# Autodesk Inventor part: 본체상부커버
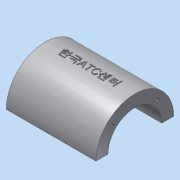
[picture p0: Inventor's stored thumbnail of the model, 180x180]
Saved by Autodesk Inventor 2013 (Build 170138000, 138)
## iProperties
Created: 2015-12
Part Number: 본체상부커버
Material: 알루미늄 6061
Document SubType Name: Modeling
Designer: mduedu
Density: 2.71 g/cm^3
Mass: 175.162 g
Surface Area: 166.445 cm^2
Volume: 64.6353 cm^3
Author: mduedu
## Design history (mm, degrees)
sketch "스케치1"
  geometry: L1 (45, 40)-(-45, 40); L2 (-45, 40)-(-45, -40); L3 (-45, -40)-(45, -40); L4 (45, -40)-(45, 40); L5 (45, 40)-(-45, -40); L6 (-45, 40)-(45, -40); 2 further points
  constraints: 12 end point, 2 midpoint, 2 parallel, 1 coincident, 1 horizontal, 1 perpendicular, 3 other
  dimensions: "d0" = 90 distance of L2.end L3.end; "d2" = 80 distance of L1.end L2.end
extrude "돌출1" new body sketch "스케치1" distance "d3" = 10; taper "d4" = 0 deg
sketch "스케치2"
  geometry: C1 r 32.5 at (80, 0); 1 further point
  constraints: 1 centre point
  dimensions: "d5" = 65 diameter of C1; "d116" = 80 distance of point (0, 0) C1.centre
extrude "돌출2" join sketch "스케치2" stored distance "d7" = 75; taper "d8" = 0 deg
sketch "스케치3"
  geometry: L1 (-27.5, -20)-(27.5, -20); L2 (27.5, -20)-(27.5, 20); L3 (27.5, 20)-(-27.5, 20); L4 (-27.5, 20)-(-27.5, -20); L5 (-27.5, -20)-(27.5, 20); L6 (27.5, -20)-(-27.5, 20); 1 further point
  constraints: 12 end point, 2 midpoint, 2 parallel, 1 horizontal, 1 perpendicular
  dimensions: "d9" = 55 distance of L2.end L3.end; "d11" = 40 distance of L1.end L2.end
extrude "돌출3" new body sketch "스케치3" stored distance "d12" = 75; taper "d13" = 0 deg
fillet "모깎기1"
fillet "모깎기2"
feature "결합1"
  node "솔리드2"
sketch "스케치4"
  geometry: L1 (-37.5, 47.5)-(37.5, 47.5) reference; L2 (32.5, 47.5)-(40.208, 10); L3 (37.5, 47.5)-(37.5, 112.5) reference; L4 (60.208, 0)-(60.208, 10) reference; L5 (60.208, 10)-(-60.208, 10) reference; 1 further point
  constraints: 2 end point, 2 point on line
  dimensions: "d15" = 5 distance from line of L2.start L3; "d117" = 20 distance from line of L2.end L4
sketch "스케치5"
  geometry: L1 (10, 35.208)-(56.729, 22.687); L2 (0, 60.208)-(10, 60.208) reference; L3 (10, -60.208)-(10, 60.208) reference; 2 further points
  constraints: 2 end point, 1 point on line, 2 other
  dimensions: "d118" = 25 distance from line of L1.start L2; "d119" = 75 deg angle of L1 L3
feature "리브1" dims "d19" = 1, "d20" = 6, "d21" = 0, "d22" = 0, "d23" = 1, "d24" = 1
feature "리브2" dims "d25" = 1, "d26" = 6, "d27" = 0, "d28" = 0, "d29" = 1, "d30" = 1
fillet "모깎기4" dims "d31" = 2
fillet "모깎기5" dims "d32" = 2
fillet "모깎기6" dims "d33" = 2
sketch "스케치6"
  geometry: L1 (0, 0)-(-32.88, 32.88); L2 (0, 0)-(-46.5, 0); A1 r 46.5 centre (0, 0) between (-32.88, 32.88) and (-46.5, 0); 5 further points
  constraints: 4 end point, 2 coincident, 2 point on circle, 1 centre point, 1 horizontal, 5 other
  dimensions: "d120" = 93 diameter of A1; "d122" = 45 deg angle of L1 L2; "d126" = 360 deg dimension on point (0, 0) point (-32.88, 32.88) (derived)
hole "구멍1" sketch "스케치6" at (-32.88, 32.88), (-32.88, -32.88), (32.88, -32.88), (32.88, 32.88) diameter "d34" = 7; stored, may be unused: countersink angle "d38" = 90 deg, drill point angle "d40" = 118 deg; dims "d35" = 6, "d36" = 12, "d37" = 3, "d39" = 8
fillet "모깎기13" dims "d131" = 3
hole "구멍2" diameter "d44" = 45; stored, may be unused: countersink angle "d48" = 90 deg, drill point angle "d50" = 118 deg; dims "d42" = 10, "d43" = 10, "d45" = 6, "d46" = 4, "d47" = 2, "d49" = 8
sketch "스케치7" dims "d52" = 26.5
  geometry: L1 (0, 0)-(32.5, 0); L2 (0, 0)-(22.981, 22.981); A1 r 32.5 centre (0, 0) between (32.5, 0) and (22.981, 22.981) reference; 3 further points
  constraints: 4 end point, 2 point on circle, 1 coincident, 1 horizontal, 1 point on line, 3 other
  dimensions: "d51" = 45 deg angle of L2 L1
hole "구멍3" sketch "스케치7" at (18.738, 18.738) diameter "d54" = 2.459; stored, may be unused: countersink angle "d58" = 90 deg, drill point angle "d60" = 118 deg; dims "d55" = 8, "d56" = 4, "d57" = 2, "d59" = 10
sketch "스케치9"
  geometry: L1 (-75, -110)-(75, -110); L2 (75, -110)-(75, 0); L3 (75, 0)-(-75, 0); L4 (-75, 0)-(-75, -110); L5 (-60.208, -80)-(60.208, -80) reference; C1 r 32.5 at (0, 0) reference; 2 further points
  constraints: 8 end point, 2 parallel, 1 coincident, 1 horizontal, 1 midpoint, 1 perpendicular
  dimensions: "d148" = 30 distance between parallel lines of L5 L1; "d159" = 150 distance between parallel lines of L2 L4
extrude "돌출5" cut sketch "스케치9" stored distance "d73" = 0; taper "d74" = 0 deg
node "작업 평면3"
sketch "스케치17" dims "d2" = 80
  geometry: 2 further points
  constraints: 1 coincident, 1 other
feature "엠보싱1" sketch "스케치17" dims "d0" = 90, "d2" = 80, "d150" = 0.5, "d151" = 0
node "솔리드1"
mirror "대칭1"
mirror "대칭2"
pattern_circular "원형 패턴1" dims angle "d62" = 360 deg
mirror "대칭3"
